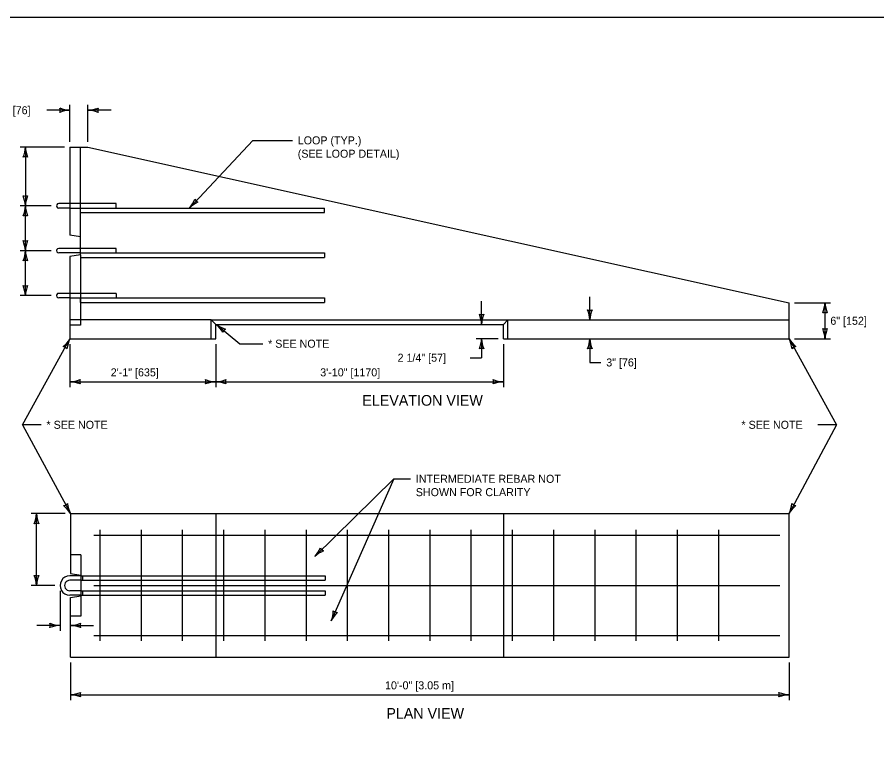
# Model space of a CAD drawing. Extents: x 49991.4 to 50021, y 49987.6 to 50011.4.
# Drawn here: x 50006.04 to 50012.48, y 49993.49 to 49999 of the extents above; entities that cross this region are included whole.
import ezdxf

# ---------------------------------------------------------------- set-up
doc = ezdxf.new("R2010")
doc.units = 0
for name, color, linetype in [('Level 1', 7, 'Continuous'), ('Level 2', 7, 'Continuous'), ('Level 3', 7, 'Continuous'), ('Level 4', 7, 'Continuous')]:
    doc.layers.add(name, color=color, linetype=linetype)

msp = doc.modelspace()

# ---------------------------------------------------------------- linework, layer by layer
at = {"layer": 'Level 1'}
for p, q in [((50006.4312, 49998.0259), (50006.5659, 49998.0259)), ((50006.4312, 49998.0259), (50006.4312, 49997.3644)), ((50006.5659, 49998.0259), (50011.8232, 49996.8583)), ((50006.4312, 49997.6021), (50006.3474, 49997.6022)), ((50006.4312, 49997.5686), (50006.3474, 49997.5686)), ((50006.5099, 49997.3524), (50006.4312, 49997.3644)), ((50006.5099, 49997.2181), (50006.5099, 49997.3524)), ((50006.5099, 49997.266), (50006.3474, 49997.266)), ((50006.5099, 49997.2322), (50006.3474, 49997.2324)), ((50006.5099, 49997.2181), (50006.4312, 49997.2062)), ((50006.4312, 49997.2062), (50006.4312, 49996.5882)), ((50006.4312, 49996.9291), (50006.3474, 49996.9292)), ((50006.4312, 49996.8955), (50006.3474, 49996.8956)), ((50011.8232, 49996.5889), (50011.8232, 49996.8583)), ((50007.4903, 49996.7303), (50007.524, 49996.6967)), ((50007.4903, 49996.7303), (50009.7146, 49996.7303)), ((50007.4903, 49996.589), (50007.4903, 49996.7303)), ((50009.6808, 49996.6967), (50009.7146, 49996.7303)), ((50009.7146, 49996.5889), (50009.7146, 49996.7303)), ((50007.5239, 49996.589), (50007.524, 49996.6967)), ((50007.524, 49996.6967), (50009.6808, 49996.6967)), ((50009.6808, 49996.5889), (50009.6808, 49996.6967)), ((50006.4312, 49996.5882), (50007.5239, 49996.589)), ((50009.6808, 49996.5889), (50011.8232, 49996.5889)), ((50006.4346, 49995.279), (50011.8232, 49995.279)), ((50006.4346, 49995.279), (50006.4346, 49994.8292)), ((50011.8232, 49994.201), (50011.8232, 49995.279)), ((50006.6554, 49995.1562), (50006.6554, 49994.3235)), ((50006.9646, 49995.1562), (50006.9646, 49994.3235)), ((50007.2738, 49995.1562), (50007.2738, 49994.3235)), ((50007.583, 49995.1562), (50007.583, 49994.3235)), ((50007.8922, 49995.1562), (50007.8922, 49994.3235)), ((50008.2014, 49995.1562), (50008.2014, 49994.3235)), ((50008.5106, 49995.1562), (50008.5106, 49994.3235)), ((50008.8198, 49995.1562), (50008.8198, 49994.3235)), ((50009.129, 49995.1562), (50009.129, 49994.3235)), ((50009.4382, 49995.1562), (50009.4382, 49994.3235)), ((50009.7474, 49995.1562), (50009.7474, 49994.3235)), ((50010.0566, 49995.1562), (50010.0566, 49994.3235)), ((50010.3658, 49995.1562), (50010.3658, 49994.3235)), ((50010.675, 49995.1562), (50010.675, 49994.3235)), ((50010.9842, 49995.1562), (50010.9842, 49994.3235)), ((50011.2934, 49995.1562), (50011.2934, 49994.3235)), ((50006.6113, 49995.1162), (50011.7543, 49995.1162)), ((50006.5132, 49994.8117), (50006.4299, 49994.8118)), ((50006.4346, 49994.8292), (50006.5132, 49994.8173)), ((50006.5132, 49994.8173), (50006.5132, 49994.6617)), ((50006.5132, 49994.7781), (50006.4299, 49994.7782)), ((50006.6113, 49994.7398), (50011.7543, 49994.7398)), ((50006.5132, 49994.7005), (50006.4299, 49994.7003)), ((50006.5132, 49994.6669), (50006.4299, 49994.6667)), ((50006.4346, 49994.6495), (50006.5132, 49994.6617)), ((50006.4346, 49994.201), (50006.4346, 49994.6495)), ((50006.6113, 49994.3635), (50011.7543, 49994.3635)), ((50006.4346, 49994.201), (50011.8232, 49994.201))]:
    msp.add_line(p, q, dxfattribs=at)
msp.add_lwpolyline([(49999.3835, 49998.9992), (50016.7501, 49998.9992), (50016.7501, 49987.7988), (49999.3835, 49987.7988)], close=True, dxfattribs=at)
for centre, major_axis, ratio in [((50006.3474, 49997.5854), (0.0168, 0), 0.9994), ((50006.3474, 49997.2492), (0.0168, 0), 0.9994), ((50006.3474, 49996.9124), (0.0168, 0), 0.9994), ((50006.4299, 49994.7393), (0.0725, 0), 0.999993), ((50006.4299, 49994.7393), (0.0389, 0), 0.999993)]:
    msp.add_ellipse(centre, major_axis=major_axis, ratio=ratio, start_param=1.570796, end_param=4.712389, dxfattribs=at)
at = {"layer": 'Level 3'}
for p, q in [((50006.4312, 49998.0659), (50006.4312, 49998.3417)), ((50006.5659, 49998.0659), (50006.5659, 49998.3417)), ((50006.4312, 49998.3017), (50006.2577, 49998.3017)), ((50006.7393, 49998.3017), (50006.5659, 49998.3017)), ((50006.3912, 49998.0259), (50006.0569, 49998.0259)), ((50006.0969, 49998.0259), (50006.0969, 49997.5853)), ((50007.327, 49997.5686), (50007.8018, 49998.0759)), ((50007.8018, 49998.0759), (50008.0994, 49998.0759)), ((50006.2906, 49997.5853), (50006.0569, 49997.5853)), ((50006.0969, 49997.249), (50006.0969, 49997.5853)), ((50006.2906, 49997.249), (50006.0569, 49997.249)), ((50006.0969, 49996.9123), (50006.0969, 49997.249)), ((50006.2907, 49996.9123), (50006.0569, 49996.9123)), ((50009.5179, 49996.6967), (50009.5179, 49996.8702)), ((50010.3297, 49996.7303), (50010.3297, 49996.9038)), ((50011.8632, 49996.8583), (50012.1327, 49996.8583)), ((50012.0927, 49996.5889), (50012.0927, 49996.8583)), ((50007.529, 49996.6967), (50007.7061, 49996.5517)), ((50006.0753, 49995.944), (50006.4312, 49996.5882)), ((50006.4312, 49996.5482), (50006.4312, 49996.227)), ((50007.5239, 49996.549), (50007.524, 49996.227)), ((50007.7061, 49996.5517), (50007.8769, 49996.5517)), ((50009.6408, 49996.5889), (50009.4779, 49996.5889)), ((50009.5179, 49996.5889), (50009.5179, 49996.4467)), ((50009.6808, 49996.5489), (50009.6808, 49996.227)), ((50010.3297, 49996.5889), (50010.3297, 49996.4112)), ((50011.8232, 49996.5889), (50012.1795, 49995.944)), ((50011.8632, 49996.5889), (50012.1327, 49996.5889)), ((50009.4323, 49996.4467), (50009.5179, 49996.4467)), ((50010.3297, 49996.4112), (50010.4124, 49996.4112)), ((50006.4312, 49996.267), (50007.5238, 49996.267)), ((50007.5238, 49996.267), (50009.6806, 49996.267)), ((50006.2153, 49995.944), (50006.0753, 49995.944)), ((50006.0753, 49995.944), (50006.4346, 49995.279)), ((50012.1795, 49995.944), (50011.8232, 49995.279)), ((50012.1795, 49995.944), (50012.0395, 49995.944)), ((50008.2665, 49994.957), (50008.8607, 49995.539)), ((50008.8607, 49995.539), (50008.3903, 49994.4741)), ((50008.8607, 49995.539), (50008.9844, 49995.539)), ((50006.3946, 49995.2788), (50006.1409, 49995.2788)), ((50006.1809, 49994.7394), (50006.1809, 49995.2788)), ((50006.3174, 49994.7394), (50006.1409, 49994.7394)), ((50006.3574, 49994.6993), (50006.3574, 49994.4001)), ((50006.3574, 49994.4401), (50006.184, 49994.4401)), ((50006.4346, 49994.4401), (50006.608, 49994.4401)), ((50006.4346, 49994.161), (50006.4346, 49993.881)), ((50011.8232, 49994.161), (50011.8232, 49993.881)), ((50006.4346, 49993.921), (50011.8232, 49993.921))]:
    msp.add_line(p, q, dxfattribs=at)
for centre, radius, start, end in [((50006.4403, 49998.5239), 0.2223, 247.45601, 267.63952), ((50006.303, 49998.3017), 0.0548, 342.13882, 17.86118), ((50006.4427, 49998.069), 0.233, 92.82731, 112.07716), ((50006.5545, 49998.5344), 0.233, 272.82731, 292.07716), ((50006.5568, 49998.0796), 0.2223, 67.45601, 87.63952), ((50006.6942, 49998.3017), 0.0548, 162.13882, 197.86118), ((50005.8747, 49998.0351), 0.2223, 337.45601, 357.63952), ((50006.3296, 49998.0374), 0.233, 182.82731, 202.07716), ((50006.0969, 49997.8977), 0.0548, 72.13882, 107.86118), ((50006.0969, 49997.7135), 0.0548, 252.13882, 287.86118), ((50005.8641, 49997.5738), 0.233, 2.82731, 22.07716), ((50006.319, 49997.5762), 0.2223, 157.45601, 177.63952), ((50007.1493, 49997.7193), 0.233, 319.71835, 338.9682), ((50007.4146, 49997.6622), 0.0548, 209.02986, 244.75222), ((50005.8747, 49997.5945), 0.2223, 337.45601, 357.63952), ((50006.3296, 49997.5968), 0.233, 182.82731, 202.07716), ((50007.4829, 49997.4101), 0.2223, 114.34705, 134.53056), ((50006.0969, 49997.4571), 0.0548, 72.13882, 107.86118), ((50006.0969, 49997.3772), 0.0548, 252.13882, 287.86118), ((50005.8641, 49997.2375), 0.233, 2.82731, 22.07716), ((50006.319, 49997.2399), 0.2223, 157.45601, 177.63952), ((50005.8747, 49997.2582), 0.2223, 337.45601, 357.63952), ((50006.3296, 49997.2605), 0.233, 182.82731, 202.07716), ((50006.0969, 49997.1208), 0.0548, 72.13882, 107.86118), ((50006.0969, 49997.0405), 0.0548, 252.13882, 287.86118), ((50005.8641, 49996.9008), 0.233, 2.82731, 22.07716), ((50006.319, 49996.9032), 0.2223, 157.45601, 177.63952), ((50010.3297, 49996.8585), 0.0548, 252.13882, 287.86118), ((50010.097, 49996.7188), 0.233, 2.82731, 22.07716), ((50010.5519, 49996.7212), 0.2223, 157.45601, 177.63952), ((50011.8705, 49996.8675), 0.2223, 337.45601, 357.63952), ((50012.3254, 49996.8698), 0.233, 182.82731, 202.07716), ((50009.5179, 49996.8249), 0.0548, 252.13882, 287.86118), ((50009.2851, 49996.6852), 0.233, 2.82731, 22.07716), ((50009.74, 49996.6876), 0.2223, 157.45601, 177.63952), ((50012.0927, 49996.7301), 0.0548, 72.13882, 107.86118), ((50007.3812, 49996.5307), 0.2223, 28.13182, 48.31533), ((50007.6676, 49996.884), 0.233, 233.50312, 252.75297), ((50007.6282, 49996.6155), 0.0548, 122.81463, 158.53699), ((50012.0927, 49996.7171), 0.0548, 252.13882, 287.86118), ((50011.8599, 49996.5774), 0.233, 2.82731, 22.07716), ((50012.3148, 49996.5798), 0.2223, 157.45601, 177.63952), ((50006.2411, 49996.7036), 0.2223, 308.53894, 328.72245), ((50006.6404, 49996.4858), 0.233, 153.91024, 173.16009), ((50009.2957, 49996.5981), 0.2223, 337.45601, 357.63952), ((50009.7506, 49996.6004), 0.233, 182.82731, 202.07716), ((50010.1076, 49996.5981), 0.2223, 337.45601, 357.63952), ((50010.5625, 49996.6004), 0.233, 182.82731, 202.07716), ((50011.6243, 49996.4895), 0.2223, 6.37617, 26.55968), ((50012.0213, 49996.7115), 0.233, 211.74747, 230.99732), ((50006.3692, 49996.476), 0.0548, 43.22175, 78.94411), ((50009.5179, 49996.4607), 0.0548, 72.13882, 107.86118), ((50010.3297, 49996.4607), 0.0548, 72.13882, 107.86118), ((50011.8852, 49996.4767), 0.0548, 101.05898, 136.78134), ((50006.4197, 49996.4997), 0.233, 272.82731, 292.07716), ((50006.5594, 49996.267), 0.0548, 162.13882, 197.86118), ((50007.5331, 49996.4891), 0.2223, 247.45601, 267.63952), ((50007.3957, 49996.267), 0.0548, 342.13882, 17.86118), ((50007.5125, 49996.4997), 0.233, 272.82731, 292.07716), ((50007.6522, 49996.267), 0.0548, 162.13882, 197.86118), ((50009.6899, 49996.4891), 0.2223, 247.45601, 267.63952), ((50009.5525, 49996.267), 0.0548, 342.13882, 17.86118), ((50006.422, 49996.0449), 0.2223, 67.45601, 87.63952), ((50007.5355, 49996.0343), 0.233, 92.82731, 112.07716), ((50007.5148, 49996.0449), 0.2223, 67.45601, 87.63952), ((50009.6923, 49996.0343), 0.233, 92.82731, 112.07716), ((50006.3736, 49995.3918), 0.0548, 280.51907, 316.24143), ((50006.2353, 49995.1583), 0.233, 31.20756, 50.45741), ((50006.6343, 49995.3765), 0.2223, 185.83626, 206.01977), ((50011.6126, 49995.3788), 0.233, 334.64538, 353.89522), ((50012.0146, 49995.166), 0.2223, 129.27408, 149.45758), ((50011.8837, 49995.392), 0.0548, 223.95688, 259.67924), ((50005.9587, 49995.288), 0.2223, 337.45601, 357.63952), ((50006.4136, 49995.2903), 0.233, 182.82731, 202.07716), ((50006.1809, 49995.1506), 0.0548, 72.13882, 107.86118), ((50008.0954, 49995.1152), 0.233, 317.23463, 336.48448), ((50008.4154, 49994.7919), 0.2223, 111.86333, 132.04684), ((50008.3581, 49995.0468), 0.0548, 206.54614, 242.2685), ((50006.1809, 49994.8676), 0.0548, 252.13882, 287.86118), ((50005.9481, 49994.7279), 0.233, 2.82731, 22.07716), ((50006.403, 49994.7303), 0.2223, 157.45601, 177.63952), ((50008.1728, 49994.5576), 0.233, 338.99627, 358.24612), ((50008.4421, 49994.5914), 0.0548, 228.30778, 264.03014), ((50008.5898, 49994.376), 0.2223, 133.62497, 153.80848), ((50006.3666, 49994.6622), 0.2223, 247.45601, 267.63952), ((50006.2292, 49994.4401), 0.0548, 342.13882, 17.86118), ((50006.3689, 49994.2074), 0.233, 92.82731, 112.07716), ((50006.4231, 49994.6728), 0.233, 272.82731, 292.07716), ((50006.4254, 49994.218), 0.2223, 67.45601, 87.63952), ((50006.5628, 49994.4401), 0.0548, 162.13882, 197.86118), ((50006.4231, 49994.1537), 0.233, 272.82731, 292.07716), ((50006.4254, 49993.6989), 0.2223, 67.45601, 87.63952), ((50006.5628, 49993.921), 0.0548, 162.13882, 197.86118), ((50011.8323, 49994.1432), 0.2223, 247.45601, 267.63952), ((50011.6949, 49993.921), 0.0548, 342.13882, 17.86118), ((50011.8347, 49993.6883), 0.233, 92.82731, 112.07716)]:
    msp.add_arc(centre, radius, start, end, dxfattribs=at)
at = {"layer": 'Level 4'}
for p, q in [((50006.5099, 49997.3524), (50006.5098, 49998.0259)), ((50006.7768, 49997.6021), (50006.4312, 49997.6021)), ((50006.4312, 49997.5686), (50008.3405, 49997.5686)), ((50006.5077, 49997.5686), (50006.5077, 49997.5349)), ((50006.7768, 49997.5686), (50006.7768, 49997.6021)), ((50008.3405, 49997.5349), (50008.3405, 49997.5686)), ((50006.5077, 49997.5349), (50008.3405, 49997.5349)), ((50006.7768, 49997.266), (50006.5099, 49997.266)), ((50006.7768, 49997.2322), (50006.7768, 49997.266)), ((50006.5099, 49997.2181), (50006.5098, 49996.6901)), ((50006.5099, 49997.2322), (50008.3405, 49997.2322)), ((50006.5099, 49997.1986), (50008.3405, 49997.1986)), ((50008.3405, 49997.2322), (50008.3405, 49997.1986)), ((50006.7769, 49996.9291), (50006.4312, 49996.9291)), ((50006.7769, 49996.9291), (50006.7769, 49996.8955)), ((50006.4312, 49996.8955), (50008.3405, 49996.8955)), ((50006.5077, 49996.8955), (50006.5077, 49996.8618)), ((50006.5077, 49996.8618), (50008.3405, 49996.8618)), ((50008.3405, 49996.8955), (50008.3405, 49996.8618)), ((50007.4903, 49996.7303), (50006.4312, 49996.7303)), ((50009.7146, 49996.7303), (50011.8232, 49996.7303)), ((50006.5098, 49996.6901), (50006.4312, 49996.6901)), ((50007.524, 49995.279), (50007.524, 49994.201)), ((50009.6808, 49995.279), (50009.6808, 49994.201)), ((50006.5132, 49994.9683), (50006.4346, 49994.9683)), ((50006.5132, 49994.9683), (50006.5132, 49994.5104)), ((50006.5132, 49994.8117), (50008.3454, 49994.8117)), ((50006.5274, 49994.7781), (50006.5274, 49994.8117)), ((50008.3454, 49994.8117), (50008.3454, 49994.7781)), ((50006.5132, 49994.7781), (50008.3454, 49994.7781)), ((50006.5132, 49994.7005), (50008.3454, 49994.7005)), ((50006.5274, 49994.6669), (50006.5274, 49994.7005)), ((50008.3454, 49994.7005), (50008.3454, 49994.6669)), ((50006.5132, 49994.6669), (50008.3454, 49994.6669)), ((50006.5132, 49994.5104), (50006.4346, 49994.5104))]:
    msp.add_line(p, q, dxfattribs=at)

# ---------------------------------------------------------------- texts
at = {"layer": 'Level 2'}
for s, height, p in [('3" [76]', 0.06, (50005.9066, 49998.2717)), ('LOOP (TYP.)', 0.06, (50008.1394, 49998.0459)), ('(SEE LOOP DETAIL) ', 0.06, (50008.1394, 49997.9459)), ('6" [152]', 0.06, (50012.1327, 49996.6936)), ('* SEE NOTE', 0.06, (50007.9169, 49996.5217)), ('2 1/4" [57]', 0.06, (50008.8878, 49996.4167)), ('3" [76]', 0.06, (50010.4524, 49996.3812)), ('2\'-1" [635]', 0.06, (50006.737, 49996.307)), ('3\'-10" [1170]', 0.06, (50008.3079, 49996.307)), ('ELEVATION VIEW', 0.079999, (50008.6235, 49996.087)), ('* SEE NOTE', 0.06, (50006.2553, 49995.914)), ('* SEE NOTE', 0.06, (50011.4661, 49995.914)), ('INTERMEDIATE REBAR NOT', 0.06, (50009.0244, 49995.509)), ('SHOWN FOR CLARITY', 0.06, (50009.0244, 49995.409)), ('10\'-0" [3.05 m]', 0.06, (50008.7939, 49993.961)), ('PLAN VIEW', 0.08, (50008.8036, 49993.741))]:
    msp.add_text(s, height=height, dxfattribs=at).set_placement(p)

doc.saveas('drawing.dxf')
